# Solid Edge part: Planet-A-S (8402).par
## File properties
Title: Planet A/S
Author: DESYS
Template: Normal.par
Last saved by: s.pallini
Revision: 28
Application: Solid Edge
Tipo di contenuto documento: 0
Precisione: 0,990
Document Number: 8402
Revision: 0
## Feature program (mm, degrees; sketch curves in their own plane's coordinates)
lofted protrusion "unnamed LoftedProtrusion 1"
sketch for "unnamed Protrusion 1" plane through (0, 0, 445) normal (0, 0, 1) x-axis (1, 0, 0)
  line (-270.5689, -135) -> (-133.6974, -135)
  line (-270.5689, 135) -> (-270.5689, -135)
  line (-270.5689, 135) -> (-133.6974, 135)
  dimension (linear) = 270.5689
extrude "unnamed Protrusion 1" add to key point along -normal
sketch for "unnamed Cutout 1" plane through (0, 0, 0) normal (0, -1, 0) x-axis (1, 0, 0)
  line (-270.5689, 445) -> (211.175, 360)
extrude "unnamed Cutout 1" cut through
sketch for "ExtrudedCutout_2" plane through (0, 0, 430) normal (0, 0, 1) x-axis (1, 0, 0)
  circle centre (7.5196, 0) radius 154.0895
extrude "ExtrudedCutout_2" cut finite 110 along -normal
lofted cutout "unnamed LoftedCutout 1"
sketch for "ExtrudedCutout_3" plane through (0, 0, 0) normal (0, -1, 0) x-axis (1, 0, 0)
  line (-255.5689, 180) -> (-255.5689, -23.5209)
  line (-270.5689, 180) -> (-255.5689, 180)
  line (-270.5689, 395) -> (-270.5689, 180)
  line (-270.5689, 395) -> (-174.5528, 395)
  arc centre (-38.4455, 309.6496) radius 160.6546 from (-174.5528, 395) to (-95.4684, 159.4555) ccw
  line (-95.4684, 159.4555) -> (-95.4684, 0)
  dimension (linear) = 270.5689
extrude "ExtrudedCutout_3" cut finite 210 symmetric
sketch for "unnamed Cutout 2" plane through (0, 0, 0) normal (0, 0, 1) x-axis (1, 0, 0)
  line (-95.4684, -105) -> (8.5066, -95.764)
  arc centre (-2.9504, 0) radius 96.4469 from (8.5066, 95.764) to (8.5066, -95.764) cw
  line (-95.4684, 105) -> (8.5066, 95.764)
  line (-95.4684, 105) -> (-95.4684, -105)
extrude "unnamed Cutout 2" cut to key point along +normal
sketch for "ExtrudedProtrusion_2" plane through (0, 0, 190) normal (0, 0, 1) x-axis (1, 0, 0)
  line (-90, -70) -> (60, -70)
  line (60, -70) -> (60, 70)
  line (60, 70) -> (-90, 70)
  line (-90, 70) -> (-90, -70)
  dimension (linear) = 90
  dimension (linear) = 60
extrude "ExtrudedProtrusion_2" add finite 180 along -normal  Treatment1_DraftAngle = 5 deg
fillet "Rotondo_1" radius 40
fillet "Rotondo_2" radius 30
sketch for "unnamed Cutout 3" plane through (-270.5689, 0, 205) normal (-1, 0, 0) x-axis (0, -1, 0)
  line (-90, -25) -> (90, -25)
extrude "unnamed Cutout 3" cut through along -normal
sketch for "ExtrudedProtrusion_3" plane through (-180.5689, 0, 205) normal (-1, 0, 0) x-axis (0, -1, 0)
  circle centre (0, -25) radius 50
extrude "ExtrudedProtrusion_3" add through along -normal  Profile_Plane1_Distance = 90 mm
sketch for "ExtrudedCutout_6" plane through (0, 0, 0) normal (0, -1, 0) x-axis (1, 0, 0)
  line (50, 190) -> (33.6666, 61.5312)
  arc centre (3.9062, 65.3149) radius 30 from (3.9062, 35.3149) to (33.6666, 61.5312) ccw
  line (-34.4205, 35.3149) -> (3.9062, 35.3149)
  arc centre (-34.4205, 65.3149) radius 30 from (-63.3356, 57.3198) to (-34.4205, 35.3149) ccw
  line (-63.3356, 57.3198) -> (-84.6468, 160.6314)
  line (-84.6468, 160.6314) -> (-147.9995, 220.4026)
  line (-147.9995, 220.4026) -> (-125.2315, 220.4026)
  line (-125.2315, 220.4026) -> (-67.5978, 188.5269)
  line (-46.1658, 66.9955) -> (-67.5978, 188.5269)
  arc centre (-38.2874, 68.3848) radius 8 from (-46.1658, 66.9955) to (-38.2874, 60.3848) ccw
  line (-33.9784, 60.3848) -> (-38.2874, 60.3848)
  arc centre (-33.9784, 64.3848) radius 4 from (-33.9784, 60.3848) to (-30.0285, 65.016) ccw
  line (-50, 190) -> (-30.0285, 65.016)
extrude "ExtrudedCutout_6" cut finite 100 symmetric
sketch for "unnamed Cutout 4" plane through (-180.5689, 0, 180) normal (-1, 0, 0) x-axis (0, -1, 0)
  circle centre (0, 0) radius 40
extrude "unnamed Cutout 4" cut to key point along -normal
sketch for "unnamed Cutout 5" plane through (-125.2315, 0, 169.4609) normal (-1, 0, 0) x-axis (0, -1, 0)
  arc centre (0, 10.5391) radius 40 from (35.2415, 29.4609) to (-35.2415, 29.4609) cw
  line (-35.2415, 29.4609) -> (35.2415, 29.4609)
extrude "unnamed Cutout 5" cut through along -normal
fillet "Rotondo_3" radius 10
fillet "Rotondo_4" radius 10
fillet "Rotondo_5" radius 30
fillet "Rotondo_6" radius 5
fillet "Rotondo_7" radius 15
fillet "Rotondo_8" radius 40
fillet "Rotondo_9" radius 10
fillet "Rotondo_10" radius 20
fillet "Rotondo_12" radius 5
sketch for "unnamed Protrusion 2" plane through (-270.5689, 0, 204.4547) normal (-1, 0, 0) x-axis (0, -1, 0)
  circle centre (0, 170.5453) radius 35
extrude "unnamed Protrusion 2" add through along -normal
sketch for "ExtrudedCutout_9" plane through (-270.5689, 0, 204.4547) normal (-1, 0, 0) x-axis (0, -1, 0)
  circle centre (0, 170.5453) radius 27.5
extrude "ExtrudedCutout_9" cut finite 80 along -normal
fillet "unnamed Round 1"
sketch for "Foro_1" plane through (-20.7751, 0.5154, 400.9258) normal (0.173758, 0, 0.984788) x-axis (0, -1, 0)
  hole centre (90.5154, -181.7334) bore radius 10
hole "Foro_1" diameter 20 through
sketch for "unnamed Hole 1" plane through (-20.7751, 0.5154, 400.9258) normal (0.173758, 0, 0.984788) x-axis (0, -1, 0)
  hole centre (-89.4846, -181.7334) bore radius 10
hole "unnamed Hole 1" through
pattern "unnamed Pattern 1" of "Foro_1", "unnamed Hole 1"
fillet "Rotondo_14" radius 2
sketch for "unnamed Protrusion 3" plane through (-58.4661, 0, 0) normal (0, 0, -1) x-axis (1, 0, 0)
  circle centre (-122.1028, 0) radius 50
extrude "unnamed Protrusion 3" add to key point along -normal
sketch for "RevolvedProtrusion_1" plane through (-180.5689, 0, 205) normal (-1, 0, 0) x-axis (0, -1, 0)
  arc centre (0, -25) radius 40 from (-40, -25) to (40, -25) cw
  line (40, -25) -> (50, -25)
  arc centre (0, -25) radius 50 from (28.3799, 16.1653) to (50, -25) cw
  arc centre (0, -25) radius 50 from (-28.3799, 16.1653) to (28.3799, 16.1653) cw
  arc centre (0, -25) radius 50 from (-28.3799, 16.1653) to (-50, -25) ccw
  line (-50, -25) -> (-40, -25)
revolve "RevolvedProtrusion_1" add finite 90 deg
sketch for "unnamed Cutout 6" plane through (-181.006, 0, 0) normal (0, 0, -1) x-axis (0, 1, 0)
  circle centre (0, 0.4372) radius 40
extrude "unnamed Cutout 6" cut to key point along -normal
sketch for "unnamed Cutout 7" plane through (-180.5689, 0, 0) normal (1, 0, 0) x-axis (0, 1, 0)
  line (40, 180) -> (-40, 180)
extrude "unnamed Cutout 7" cut through along +normal
sketch for "ExtrudedProtrusion_6" plane through (-261.006, 0, 90) normal (1, 0, 0) x-axis (0, -1, 0)
  line (-99.4987, -80) -> (-105, -80)
  line (-105, -90) -> (-105, -80)
  line (-90, -90) -> (-105, -90)
  arc centre (0, -90) radius 90 from (90, -90) to (-90, -90) ccw
  line (105, -90) -> (90, -90)
  line (105, -90) -> (105, -80)
  line (105, -80) -> (99.4987, -80)
  arc centre (0, -90) radius 100 from (99.4987, -80) to (-99.4987, -80) ccw
extrude "ExtrudedProtrusion_6" add finite 32 along +normal
fillet "unnamed Round 2"
fillet "Rotondo_16" radius 8
sketch for "RevolvedCutout_1" plane through (0, 0, 0) normal (0, -1, 0) x-axis (1, 0, 0)
revolve "RevolvedCutout_1" cut finite 240 deg
sketch for "ExtrudedProtrusion_7" #1 plane through (-121.6681, 0, 0) normal (1, 0, 0) x-axis (0, 1, 0)
sketch for "ExtrudedProtrusion_7" #2 plane through (-121.6681, 0, 0) normal (1, 0, 0) x-axis (0, 1, 0)
extrude "ExtrudedProtrusion_7" add to key point along +normal  Profile_Plane1_Distance = 121.6681 mm
fillet "Rotondo_17" radius 2
fillet "Rotondo_18" radius 5
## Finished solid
Body 1: solid body, 199 faces, 493 edges, 295 vertices.
  Faces by surface: cylinder 74, plane 48, blend 41, torus 27, sphere 8, spline 1
  Edges by curve: circle 176, line 171, intersection 108, ellipse 38
Bounding box of the edges (mm; curved faces can reach further): 483.332 x 411.824 x 443.081, from (-270.5689, -205.913, 0) to (212.7632, 205.9105, 443.0811).
Cylindrical faces by radius (mm): R2 x1, R4 x1, R5 x24, R8 x5, R10 x16, R20 x2, R27.5 x1, R30 x8, R35 x1, R40 x8, R50 x2, R90 x1, R96.4469 x1, R100 x1, R154.0895 x1, R160.6546 x1
Toroidal faces (ring radius, tube radius in mm): R-330.5689 r550 x1, R5 r5 x2, R8 r2 x1, R9 r5 x2, R10 r5 x8, R12 r2 x2, R13 r5 x2, R30 r5 x1, R60 r20 x2, R76.4469 r20 x1, R95 r5 x1, R99.549 r79.5312 x1, R104.4469 r8 x1, R180.6546 r20 x2
Spherical faces by radius (mm): R5 x2, R10 x4, R40 x1, R50 x1
Planar faces by outward normal: +x 4, +y 4, +z 3, -x 5, -y 4, -z 13, oblique 15
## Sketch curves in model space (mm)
arc centre (0, -11.7882, 380.2163) radius 200 from (0, 50, 190) through (0, 130.2156, 239.3797) to (0, 178.9315, 320)
arc centre (0, 11.7882, 380.2163) radius 200 from (0, -178.9315, 320) through (0, -130.2156, 239.3797) to (0, -50, 190)
arc centre (20.0352, 0, 377.3368) radius 200 from (-171.5698, 0, 320) through (-126.0432, 0, 240.7312) to (-50, 0, 190)
arc centre (-26.3137, 0, 406.9706) radius 230 from (186.6091, 0, 320) through (132.2405, 0, 240.3555) to (50, 0, 190)
arc centre (20, -20, 190) radius 30 from (20, -50, 190) through (41.8212, -40.5872, 190) to (50, -20, 190)
line (50, -20, 190) -> (50, 20, 190)
arc centre (20, 20, 190) radius 30 from (20, 50, 190) through (41.8212, 40.5872, 190) to (50, 20, 190)
line (20, 50, 190) -> (-45, 50, 190)
arc centre (-45, 45, 190) radius 5 from (-50, 45, 190) through (-48.4312, 48.6369, 190) to (-45, 50, 190)
line (-50, 45, 190) -> (-50, -45, 190)
arc centre (-45, -45, 190) radius 5 from (-50, -45, 190) through (-48.4312, -48.6369, 190) to (-45, -50, 190)
line (-45, -50, 190) -> (20, -50, 190)
circle centre (7.5196, 0, 320) radius 179.0895
arc centre (-330.5689, 0, 267.495) radius 550 from (190, 0, 445) through (217.2226, 0, 218.2553) to (150, 0, 0)
circle centre (0, 0, 445) radius 190
circle centre (0, 0, 0) radius 150
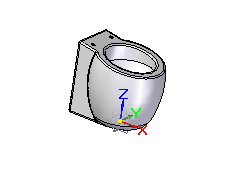
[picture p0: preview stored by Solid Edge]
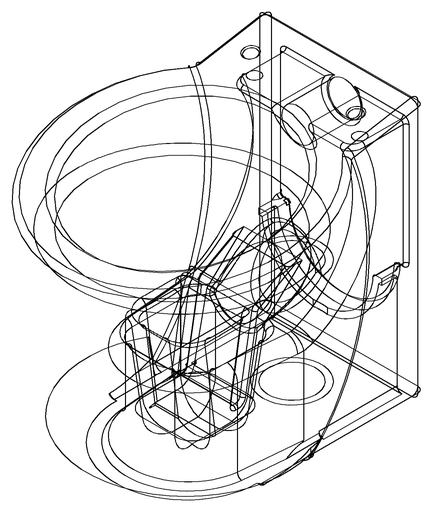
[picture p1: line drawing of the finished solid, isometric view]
